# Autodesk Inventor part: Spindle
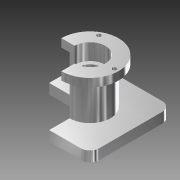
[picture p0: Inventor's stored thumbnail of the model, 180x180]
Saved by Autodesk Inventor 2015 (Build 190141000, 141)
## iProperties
Shininess: 94.0
Length Units: 11269
Angle Units: 11279
Time Units: 11290
Mass Units: 11283
Length Display Precision: 3
Angle Display Precision: 2
Created: 2004-12
Part Number: Spindle
Description: Spindle.ipt.
Document SubType Name: Modeling
Designer: DA
Material: NICU, Monel 400
Density: 8.83 g/cm^3
Appearance: Chrome
Density: 0.0
Volumn: 0.0
Area: 0.0
PropertySet Name: Model Information
Control State: 0
Master: False
Checked Out: False
ProtocolID: P00010905134112116
Protocol: P00010905134112116<@PID>[Version]<@EL>Version=2.0<@EL>[BaseView]<@EL>EnableUpdate=<@EL>InOpt=0<@EL>UpdateAll=0<@EL>OnTop=0<@EL>Left=479<@EL>Top=280<@EL>W2=350<@
Author: Autodesk
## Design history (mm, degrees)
sketch "Sketch1"
  geometry: L1 (40, -40)-(-40, -40); L2 (-40, -40)-(-40, 40); L3 (-40, 40)-(40, 40); L4 (40, 40)-(40, -40); L5 (-56, 0)-(56, 0) reference; L6 (0, 56)-(0, -56) reference
  constraints: 8 end point, 2 parallel, 1 horizontal, 1 perpendicular
  dimensions: "Side_length" = 80 distance of L1.end L2.end; "d1" = 80 distance of L2.end L3.end (= Side_length); "d2" = 40 distance between parallel lines of L2 L6 (= 0.5 x Side_length); "d3" = 40 distance between parallel lines of L3 L5 (= 0.5 x Side_length)
extrude "Extrusion1" new body sketch "Sketch1" distance "d4" = 10; taper "d5" = 0 deg
sketch "Sketch3"
  geometry: C1 r 20 at (0, 0)
  constraints: 1 centre point
  dimensions: "Shaft_hole_diam" = 40 diameter of C1
extrude "Extrusion3" join sketch "Sketch3" distance "d11" = 6; taper "d12" = 0 deg
fillet "Fillet1" dims "d16" = 9
sketch "Sketch4"
  geometry: C1 r 20 at (0, 0) reference
extrude "Extrusion4" join sketch "Sketch4" taper "d18" = 0 deg; distance "Spindle_length" = 60
sketch "Sketch5"
  geometry: L1 (0, 66)-(0, -18) reference; L2 (20, -6)-(-20, -6) reference; L3 (-20, 54)-(20, 54) reference; L4 (0, -6)-(-16, -6); L5 (-16, 6)-(-12, 6); L6 (-12, 6)-(-11, 38); L7 (-11, 38)-(-15, 38); L8 (-15, 38)-(-15, 54); L9 (0, 54)-(0, -6); L10 (-16, 6)-(-16, -6); L11 (-16, -6)-(0, -6)
  constraints: 16 end point, 3 parallel, 2 collinear, 2 midpoint, 2 point on line, 1 perpendicular
  dimensions: "Bearing2_hole_diam" = 30 diameter of L8 L1; "Bearing1_hole_diam" = 32 diameter of L10 L1; "d22" = 4 distance of L6.end L7.end; "d23" = 4 distance of L5.start L5.end; "Bearing2_hole_depth" = 16 distance of L7.end L8.end; "Bearing1_hole_depth" = 12 distance of L5.start L4.end; "Bearing_distance" = 32 distance between parallel lines of L7 L5 (derived)
revolve "Revolution1" sketch "Sketch5" stored, may be unused: angle "d26" = 90 deg
sketch "Sketch6"
  geometry: C1 r 20 at (0, 0) reference; C2 r 28 at (0, 0)
  constraints: 1 centre point
  dimensions: "d27" = 8 radial gap between concentric circles of C2 C1
extrude "Extrusion5" join sketch "Sketch6" distance "d28" = 8; taper "d29" = 0 deg
sketch "Sketch7"
  geometry: L1 (-56, 0)-(56, 0) reference; C1 r 28 at (0, 0) reference; 1 further point
  constraints: 1 point on line
  dimensions: "d30" = 24 distance of point (24, 0) C1.centre
hole "Hole1" sketch "Sketch7" at (24, 0) diameter "d31" = 4; stored, may be unused: countersink angle "d35" = 82 deg, drill point angle "d37" = 118 deg; dims "d32" = 6, "d33" = 4, "d34" = 2, "d36" = 8
pattern_circular "Circular Pattern2" dims angle "d40" = 360 deg
sketch "Sketch9"
  geometry: L1 (0, 0)-(-102.595, 0); L2 (-102.595, 0)-(-102.595, -117.036); L3 (-102.595, -117.036)-(0, -117.036); L4 (0, -117.036)-(0, 0); C1 r 2 at (-12, -20.785) reference; C2 r 15 at (0, 0) reference
  constraints: 8 end point, 2 parallel, 1 horizontal, 1 perpendicular
extrude "Extrusion7" cut sketch "Sketch9" stored distance "d43" = 10; taper "d44" = 0 deg
sketch "Sketch10"
  geometry: L1 (40, 31)-(40, -31) reference; L2 (-31, 40)-(31, 40) reference; 1 further point
  dimensions: "d60" = 9 distance from line of L1 point (31, 31); "d61" = 9 distance from line of point (31, 31) L2 (= d60)
hole "Hole2" sketch "Sketch10" at (31, 31) diameter "d46" = 8; stored, may be unused: countersink angle "d50" = 82 deg, drill point angle "d52" = 118 deg; dims "d47" = 6, "d48" = 4, "d49" = 2, "d51" = 8
pattern_linear "Rectangular Pattern1" dims "d55" = 62 (= Side_length - 2 x d60), "d58" = 62 (= Side_length - 2 x d60)
body "Solid1"
